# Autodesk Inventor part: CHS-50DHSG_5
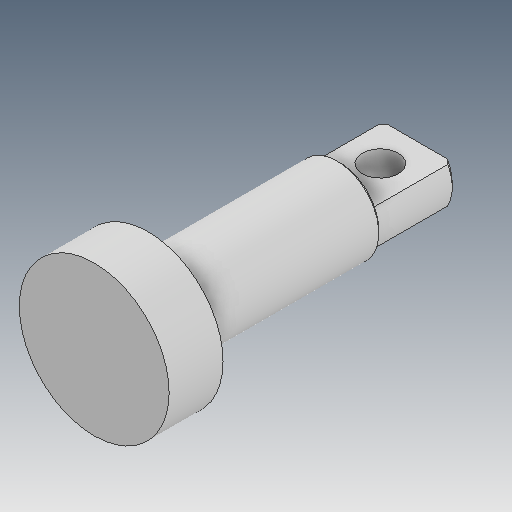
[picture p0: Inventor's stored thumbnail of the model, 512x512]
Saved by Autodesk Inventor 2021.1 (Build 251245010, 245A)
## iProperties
Created: 2019-04
Part Number: CHS-50DHSG_5
Material: Ogólny
Document SubType Name: Modeling
Designer: user
Density: 1 g/cm^3
Appearance: Domyślna
Author: user
Revision Number: ÈÎºÎ
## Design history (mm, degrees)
feature "ÊäÈë1"
node "Bryła1"
